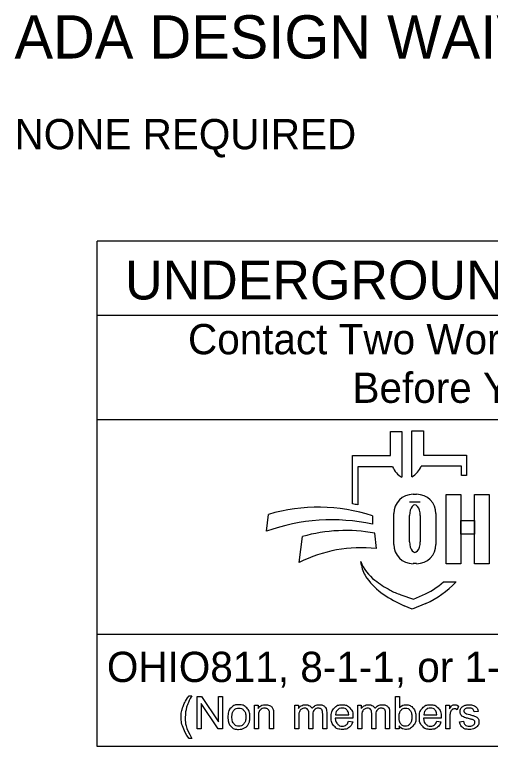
# Model space of a CAD drawing. Extents: x 0 to 34, y 0 to 22.
# Drawn here: x 1.995 to 4.196, y 2.143 to 5.529 of the extents above; entities that cross this region are included whole.
import ezdxf

# ---------------------------------------------------------------- set-up
doc = ezdxf.new("R2010")
doc.units = 0
doc.layers.add('SH_Data', color=7, linetype='Continuous')
doc.layers.add('SH_Text', color=7, linetype='Continuous')

msp = doc.modelspace()

# ---------------------------------------------------------------- linework, layer by layer
at = {"layer": 'SH_Data'}
for p, q in [((2.3775, 2.1428), (2.3775, 4.4803)), ((6.6275, 4.4803), (2.3775, 4.4803)), ((2.3775, 4.1387), (6.6275, 4.1387)), ((2.3775, 3.6553), (6.6275, 3.6553)), ((6.6275, 2.6607), (2.3775, 2.6607)), ((6.6275, 2.1428), (2.3775, 2.1428))]:
    msp.add_line(p, q, dxfattribs=at)
at = {"layer": 'SH_Text'}
for p, q in [((3.7335, 3.4883), (3.7335, 3.5998)), ((3.7335, 3.5998), (3.7872, 3.5998)), ((3.7872, 3.5998), (3.7872, 3.3877)), ((3.8329, 3.39), (3.8329, 3.6021)), ((3.8329, 3.6021), (3.8865, 3.6021)), ((3.8865, 3.6021), (3.8865, 3.4906)), ((3.5576, 3.2644), (3.5576, 3.4883)), ((3.5576, 3.4883), (3.7335, 3.4883)), ((3.8865, 3.4906), (4.0857, 3.4906)), ((4.0857, 3.4906), (4.0857, 3.3968)), ((3.5828, 3.4369), (3.5828, 3.26)), ((3.7439, 3.4369), (3.5828, 3.4369)), ((4.0625, 3.4392), (3.8761, 3.4392)), ((4.0625, 3.3968), (4.0625, 3.4392)), ((4.0857, 3.3968), (4.0625, 3.3968)), ((3.8385, 3.3091), (3.8551, 3.3091)), ((3.8718, 3.2721), (3.822, 3.2721)), ((3.7491, 3.0776), (3.7491, 3.2196)), ((3.9445, 3.2196), (3.9445, 3.0776)), ((3.1602, 3.1381), (3.1696, 3.2162)), ((3.6509, 3.2097), (3.6509, 3.1709)), ((3.822, 3.089), (3.822, 3.2114)), ((3.8718, 3.2114), (3.8718, 3.089)), ((3.6608, 3.1291), (3.6671, 3.0582)), ((3.312, 2.9936), (3.3267, 3.1137)), ((3.5997, 2.9807), (3.5967, 2.9986)), ((3.8551, 2.9882), (3.8385, 2.9882)), ((3.98, 2.9048), (4.0375, 2.9048)), ((3.7816, 2.8444), (3.841, 2.8239)), ((3.841, 2.8239), (3.8821, 2.8417)), ((3.835, 2.7769), (3.7976, 2.7934)), ((3.8983, 2.8044), (3.835, 2.7769))]:
    msp.add_line(p, q, dxfattribs=at)
for points in [[(3.991, 3.3081), (4.0589, 3.3081), (4.0589, 2.9881), (3.991, 2.9881)], [(4.1231, 3.3081), (4.1911, 3.3081), (4.1911, 2.9881), (4.1231, 2.9881)], [(4.0589, 3.1882), (4.1231, 3.1882), (4.1231, 3.1242), (4.0589, 3.1242)]]:
    msp.add_lwpolyline(points, close=True, dxfattribs=at)
for points in [[(2.8021, 2.3766), (2.8153, 2.3766)], [(2.8389, 2.2239), (2.8389, 2.3741), (2.8592, 2.3741), (2.9382, 2.2561), (2.9382, 2.3741), (2.9572, 2.3741), (2.9572, 2.2239), (2.9369, 2.2239), (2.8579, 2.3419), (2.8579, 2.2239), (2.8389, 2.2239)], [(3.7743, 2.2239), (3.7573, 2.2239), (3.7573, 2.3741), (3.7757, 2.3741), (3.7757, 2.3206)], [(3.1048, 2.2239), (3.1048, 2.3328), (3.1214, 2.3328), (3.1214, 2.3173)], [(3.2912, 2.2239), (3.2912, 2.3328), (3.3077, 2.3328), (3.3077, 2.3174)], [(3.5826, 2.2239), (3.5826, 2.3328), (3.5991, 2.3328), (3.5991, 2.3174)], [(3.9904, 2.2239), (3.9904, 2.3328), (4.007, 2.3328), (4.007, 2.3163)], [(4.0495, 2.3293), (4.043, 2.3122)], [(4.1394, 2.3046), (4.1213, 2.3022)], [(3.1233, 2.2833), (3.1233, 2.2239), (3.1048, 2.2239)], [(3.1932, 2.2908), (3.1932, 2.2239), (3.1748, 2.2239), (3.1748, 2.2901)], [(3.3097, 2.2803), (3.3097, 2.2239), (3.2912, 2.2239)], [(3.3743, 2.2871), (3.3743, 2.2239), (3.3559, 2.2239), (3.3559, 2.2946)], [(3.4388, 2.2986), (3.4388, 2.2239), (3.4203, 2.2239), (3.4203, 2.2924)], [(3.56, 2.2736), (3.4788, 2.2736)], [(3.4799, 2.2887), (3.5406, 2.2887)], [(3.601, 2.2803), (3.601, 2.2239), (3.5826, 2.2239)], [(3.6657, 2.2871), (3.6657, 2.2239), (3.6473, 2.2239), (3.6473, 2.2946)], [(3.7301, 2.2986), (3.7301, 2.2239), (3.7117, 2.2239), (3.7117, 2.2924)], [(3.968, 2.2736), (3.8868, 2.2736)], [(3.8879, 2.2887), (3.9486, 2.2887)], [(4.0088, 2.2809), (4.0088, 2.2239), (3.9904, 2.2239)], [(3.5404, 2.2591), (3.5595, 2.2567)], [(3.7743, 2.2375), (3.7743, 2.2239)], [(3.9484, 2.2591), (3.9675, 2.2567)], [(4.053, 2.2564), (4.0712, 2.2593)], [(2.8153, 2.1798), (2.8021, 2.1798)]]:
    msp.add_lwpolyline(points, dxfattribs=at)
for centre, radius, start, end in [((3.8353, 3.4736), 0.0985, 201.9296, 240.7469), ((3.7847, 3.476), 0.0985, 299.2531, 338.0704), ((3.8385, 3.2196), 0.0895, 90, 180), ((3.8551, 3.2196), 0.0895, 0, 90), ((3.4295, 2.4554), 0.8191, 79.2074, 81.0007), ((3.3997, 2.4302), 0.8191, 72.1402, 106.3144), ((3.4628, 2.2991), 0.8919, 77.8238, 109.8274), ((3.5267, 2.4094), 0.7322, 79.44, 105.8467), ((3.5987, 2.4262), 0.6357, 83.8248, 116.8021), ((3.8385, 3.0776), 0.0895, 180, 270), ((3.8551, 3.0776), 0.0895, 270, 0), ((3.7841, 3.0707), 0.2008, 201.0457, 232.5314), ((3.741, 3.0048), 0.1433, 189.6817, 216.0884), ((3.8747, 3.1022), 0.3088, 216.0884, 235.7167), ((3.9766, 3.3219), 0.5173, 232.5314, 241.794), ((3.7387, 3.1722), 0.3602, 293.4582, 312.0712), ((3.7387, 3.1722), 0.401, 293.4582, 317.8286), ((4.0412, 3.3465), 0.6044, 235.7167, 246.2325), ((3.8914, 3.1631), 0.3371, 241.794, 250.9821)]:
    msp.add_arc(centre, radius, start, end, dxfattribs=at)
for centre, start_param, end_param in [((3.8469, 3.2114), 4.712389, 7.853982), ((3.8469, 3.089), 1.570796, 4.712389)]:
    msp.add_ellipse(centre, major_axis=(0, 0.0484), ratio=0.514403, start_param=start_param, end_param=end_param, dxfattribs=at)
for points in [[(2.8021, 2.1798), (2.7869, 2.199), (2.7763, 2.2248), (2.7657, 2.2506), (2.7657, 2.2783), (2.7657, 2.3026), (2.7736, 2.325), (2.7829, 2.3509), (2.8021, 2.3766)], [(2.8153, 2.3766), (2.8029, 2.3553), (2.7989, 2.3462), (2.7927, 2.332), (2.7891, 2.3167), (2.7847, 2.2975), (2.7847, 2.2782), (2.7847, 2.2289), (2.8153, 2.1798)], [(2.9814, 2.2783), (2.9814, 2.3085), (2.9981, 2.3231), (3.0122, 2.3352), (3.0323, 2.3352), (3.0547, 2.3352), (3.069, 2.3205), (3.0832, 2.3058), (3.0832, 2.2799), (3.0832, 2.2589), (3.0769, 2.2469), (3.0706, 2.2348), (3.0586, 2.2282), (3.0466, 2.2215), (3.0323, 2.2215), (3.0095, 2.2215), (2.9954, 2.2362), (2.9814, 2.2508), (2.9814, 2.2783)], [(3.0003, 2.2783), (3.0003, 2.2574), (3.0094, 2.247), (3.0185, 2.2366), (3.0323, 2.2366), (3.046, 2.2366), (3.0551, 2.2471), (3.0642, 2.2575), (3.0642, 2.279), (3.0642, 2.2991), (3.0551, 2.3095), (3.0459, 2.3199), (3.0323, 2.3199), (3.0185, 2.3199), (3.0094, 2.3096), (3.0003, 2.2992), (3.0003, 2.2783)], [(3.1214, 2.3173), (3.1334, 2.3352), (3.156, 2.3352), (3.1659, 2.3352), (3.1741, 2.3316), (3.1823, 2.3281), (3.1864, 2.3224), (3.1905, 2.3166), (3.1922, 2.3087), (3.1932, 2.3036), (3.1932, 2.2908)], [(3.1748, 2.2901), (3.1748, 2.3013), (3.1726, 2.3069), (3.1705, 2.3125), (3.165, 2.3158), (3.1595, 2.3191), (3.1521, 2.3191), (3.1404, 2.3191), (3.1318, 2.3117), (3.1233, 2.3042), (3.1233, 2.2833)], [(3.3077, 2.3174), (3.3128, 2.3254), (3.3214, 2.3303), (3.3299, 2.3352), (3.3407, 2.3352), (3.3528, 2.3352), (3.3606, 2.3301), (3.3683, 2.3251), (3.3715, 2.3161), (3.3844, 2.3352), (3.4051, 2.3352), (3.4213, 2.3352), (3.43, 2.3262), (3.4388, 2.3172), (3.4388, 2.2986)], [(3.3559, 2.2946), (3.3559, 2.3069), (3.3514, 2.313), (3.3469, 2.3191), (3.3366, 2.3191), (3.3288, 2.3191), (3.3222, 2.315), (3.3156, 2.311), (3.3126, 2.3031), (3.3097, 2.2952), (3.3097, 2.2803)], [(3.4203, 2.2924), (3.4203, 2.3035), (3.4185, 2.3083), (3.4168, 2.3132), (3.412, 2.3162), (3.4073, 2.3191), (3.401, 2.3191), (3.3895, 2.3191), (3.3819, 2.3115), (3.3743, 2.3039), (3.3743, 2.2871)], [(3.5595, 2.2567), (3.555, 2.24), (3.5428, 2.2307), (3.5306, 2.2215), (3.5117, 2.2215), (3.4878, 2.2215), (3.4738, 2.2362), (3.4598, 2.2509), (3.4598, 2.2774), (3.4598, 2.3049), (3.474, 2.32), (3.4881, 2.3352), (3.5106, 2.3352), (3.5324, 2.3352), (3.5463, 2.3203), (3.5601, 2.3055), (3.5601, 2.2785), (3.5601, 2.2769), (3.56, 2.2736)], [(3.5406, 2.2887), (3.5394, 2.3025), (3.5337, 2.3094), (3.5249, 2.3201), (3.5108, 2.3201), (3.4981, 2.3201), (3.4894, 2.3115), (3.4808, 2.303), (3.4799, 2.2887)], [(3.5991, 2.3174), (3.6042, 2.3254), (3.6127, 2.3303), (3.6212, 2.3352), (3.6321, 2.3352), (3.6442, 2.3352), (3.6519, 2.3301), (3.6597, 2.3251), (3.6628, 2.3161), (3.6758, 2.3352), (3.6965, 2.3352), (3.7127, 2.3352), (3.7214, 2.3262), (3.7301, 2.3172), (3.7301, 2.2986)], [(3.6473, 2.2946), (3.6473, 2.3069), (3.6428, 2.313), (3.6383, 2.3191), (3.628, 2.3191), (3.6202, 2.3191), (3.6136, 2.315), (3.607, 2.311), (3.604, 2.3031), (3.601, 2.2952), (3.601, 2.2803)], [(3.7117, 2.2924), (3.7117, 2.3035), (3.7099, 2.3083), (3.7081, 2.3132), (3.7034, 2.3162), (3.6987, 2.3191), (3.6923, 2.3191), (3.6809, 2.3191), (3.6733, 2.3115), (3.6657, 2.3039), (3.6657, 2.2871)], [(3.7741, 2.2792), (3.7741, 2.2596), (3.7794, 2.2509), (3.7881, 2.2366), (3.8029, 2.2366), (3.815, 2.2366), (3.8238, 2.2471), (3.8326, 2.2576), (3.8326, 2.2784), (3.8326, 2.2998), (3.8241, 2.3099), (3.8157, 2.3201), (3.8038, 2.3201), (3.7917, 2.3201), (3.7829, 2.3096), (3.7741, 2.299), (3.7741, 2.2792)], [(3.7757, 2.3206), (3.7874, 2.3352), (3.8055, 2.3352), (3.8155, 2.3352), (3.8245, 2.3311), (3.8335, 2.3271), (3.8392, 2.3198), (3.845, 2.3124), (3.8483, 2.3021), (3.8516, 2.2918), (3.8516, 2.28), (3.8516, 2.252), (3.8378, 2.2368), (3.8239, 2.2215), (3.8046, 2.2215), (3.7853, 2.2215), (3.7743, 2.2375)], [(3.9675, 2.2567), (3.963, 2.24), (3.9508, 2.2307), (3.9386, 2.2215), (3.9196, 2.2215), (3.8958, 2.2215), (3.8818, 2.2362), (3.8678, 2.2509), (3.8678, 2.2774), (3.8678, 2.3049), (3.882, 2.32), (3.8961, 2.3352), (3.9186, 2.3352), (3.9404, 2.3352), (3.9543, 2.3203), (3.9681, 2.3055), (3.9681, 2.2785), (3.9681, 2.2769), (3.968, 2.2736)], [(3.9486, 2.2887), (3.9474, 2.3025), (3.9417, 2.3094), (3.9328, 2.3201), (3.9188, 2.3201), (3.9061, 2.3201), (3.8974, 2.3115), (3.8888, 2.303), (3.8879, 2.2887)], [(4.007, 2.3163), (4.0133, 2.3278), (4.0187, 2.3315), (4.0241, 2.3352), (4.0305, 2.3352), (4.0398, 2.3352), (4.0495, 2.3293)], [(4.043, 2.3122), (4.0363, 2.3162), (4.0295, 2.3162), (4.0235, 2.3162), (4.0187, 2.3125), (4.0139, 2.3089), (4.0119, 2.3024), (4.0088, 2.2926), (4.0088, 2.2809)], [(4.1213, 2.3022), (4.1201, 2.3106), (4.1142, 2.3153), (4.1083, 2.3201), (4.0975, 2.3201), (4.0848, 2.3201), (4.0794, 2.3159), (4.0739, 2.3116), (4.0739, 2.306), (4.0739, 2.3024), (4.0762, 2.2995), (4.0785, 2.2966), (4.0833, 2.2946), (4.086, 2.2936), (4.0996, 2.2899), (4.1192, 2.2847), (4.1269, 2.2813), (4.1347, 2.278), (4.1391, 2.2717), (4.1435, 2.2653), (4.1435, 2.2559), (4.1435, 2.2467), (4.1381, 2.2386), (4.1327, 2.2304), (4.1226, 2.226), (4.1124, 2.2215), (4.0996, 2.2215), (4.0784, 2.2215), (4.0672, 2.2303), (4.0561, 2.2391), (4.053, 2.2564)], [(4.0712, 2.2593), (4.0727, 2.2483), (4.0798, 2.2425), (4.0868, 2.2366), (4.0995, 2.2366), (4.1122, 2.2366), (4.1184, 2.2418), (4.1245, 2.247), (4.1245, 2.254), (4.1245, 2.2602), (4.1191, 2.2638), (4.1153, 2.2663), (4.1002, 2.2701), (4.0799, 2.2752), (4.072, 2.2789), (4.0642, 2.2827), (4.0601, 2.2893), (4.0561, 2.2959), (4.0561, 2.3038), (4.0561, 2.3111), (4.0594, 2.3173), (4.0628, 2.3235), (4.0685, 2.3276), (4.0728, 2.3308), (4.0803, 2.333), (4.0877, 2.3352), (4.0962, 2.3352), (4.109, 2.3352), (4.1187, 2.3315), (4.1284, 2.3278), (4.133, 2.3215), (4.1377, 2.3152), (4.1394, 2.3046)], [(3.4788, 2.2736), (3.4799, 2.2557), (3.489, 2.2462), (3.4981, 2.2366), (3.5117, 2.2366), (3.5219, 2.2366), (3.5291, 2.242), (3.5362, 2.2473), (3.5404, 2.2591)], [(3.8868, 2.2736), (3.8879, 2.2557), (3.897, 2.2462), (3.9061, 2.2366), (3.9197, 2.2366), (3.9299, 2.2366), (3.937, 2.242), (3.9442, 2.2473), (3.9484, 2.2591)]]:
    msp.add_open_spline(points, degree=3, dxfattribs=at)

# ---------------------------------------------------------------- texts
for s, height, p in [('ADA DESIGN WAIVERS', 0.2, (1.9944, 5.3256)), ('NONE REQUIRED', 0.14, (1.9944, 4.9056)), ('UNDERGROUND UTILITIES', 0.18, (2.5057, 4.2106)), ('Contact Two Working Days', 0.14, (2.7972, 3.9571)), ('Before You Dig', 0.14, (3.5583, 3.7321)), ('OHIO811, 8-1-1, or 1-800-362-2764', 0.14, (2.422, 2.4406))]:
    msp.add_text(s, height=height, dxfattribs=at).set_placement(p)

doc.saveas('drawing.dxf')
